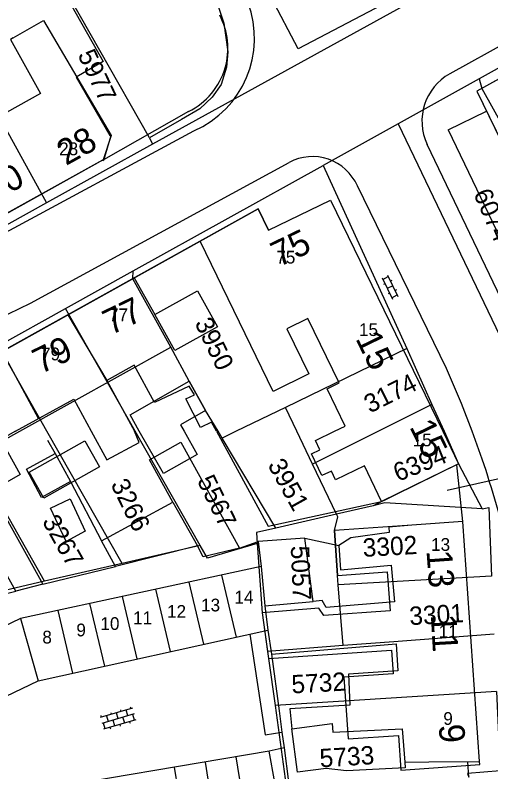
# Model space of a CAD drawing. Extents: x 148816 to 151297, y 399515 to 402500.
# Drawn here: x 150075.5 to 150122.1, y 399966.6 to 400040.8 of the extents above; entities that cross this region are included whole.
import ezdxf

# ---------------------------------------------------------------- set-up
doc = ezdxf.new("R2010")
doc.units = 0
for name, color, linetype in [('B01 Hoofdgebouw  [D] Norm', 7, 'Continuous'), ('B01 Hoofdgebouw  [T] Norm', 7, 'Continuous'), ('B01 hoofgebouw', 7, 'Continuous'), ('B02 Bijgebouw  [D] Norm', 7, 'Continuous'), ('B07 Tussenmuur  [D] Norm', 7, 'Continuous'), ('G01 perceelsgrens', 7, 'Continuous'), ('Q21 Lichtmast  Gem', 7, 'Continuous'), ('S02 Open verharding  Norm', 7, 'Continuous'), ('T04 Haag heg  [D] Gem', 7, 'Continuous'), ('V00 Kant verharding algemeen  [T] Norm', 7, 'Continuous'), ('Z01 perceelnummer', 7, 'Continuous'), ('Z02 huisnummer', 7, 'Continuous'), ('Z02 Huisnummer  [Tekst] Norm', 7, 'Continuous')]:
    doc.layers.add(name, color=color, linetype=linetype)

msp = doc.modelspace()

# ---------------------------------------------------------------- linework, layer by layer
at = {"layer": 'B01 Hoofdgebouw  [D] Norm'}
for points in [[(150089.203, 400011.428), (150093.387, 400013.755), (150095.347, 400010.23), (150091.163, 400007.903)], [(150091.769, 399998.936), (150097.495, 399988.553), (150093.962, 399987.692), (150093.404, 399988.761), (150085.371, 399986.735), (150083.977, 399989.254), (150090.972, 399993.062), (150088.691, 399997.209)], [(150076.644, 399996.281), (150079.442, 399997.83), (150080.962, 399995.081), (150078.114, 399993.508)], [(150080.934, 399993.377), (150082.403, 399990.222), (150080.521, 399989.207), (150079.001, 399992.464)], [(150100.412, 399968.636), (150075.704, 399964.466), (150076.711, 399958.311), (150101.52, 399962.506)]]:
    msp.add_lwpolyline(points, close=True, dxfattribs=at)
for points in [[(150095.261, 400000), (150094.753, 400000.902), (150093.69, 400000.385), (150092.244, 400003.168), (150093.104, 400003.582), (150092.564, 400004.416), (150089.172, 400002.813), (150087.185, 400006.482), (150084.504, 400004.986), (150087.214, 400000)], [(150075.565, 400000), (150081.291, 400003.156), (150082.98, 400000)], [(150075.565, 400000), (150074.133, 399999.183), (150076.008, 399995.773), (150073.159, 399994.123), (150078.253, 399985.013), (150075.583, 399984.329), (150071.731, 399991.226)], [(150082.98, 400000), (150084.523, 399997.214), (150087.677, 399998.889), (150087.214, 400000)], [(150095.261, 400000), (150100.32, 399990.712), (150111.437, 399993.114)], [(150114.4, 399990.81), (150112.136, 399990.597), (150112.186, 399990.089), (150108.424, 399989.559), (150107.254, 399988.797), (150107.403, 399986.406), (150112.384, 399986.884), (150112.709, 399983.298), (150105.999, 399982.72), (150105.619, 399983.407), (150104.73, 399983.306), (150103.926, 399989.538), (150099.326, 399989.212), (150099.627, 399986.745), (150076.062, 399981.658), (150066.576, 399977.116)], [(150058.071, 399966.088), (150077.78, 399975.553), (150100.278, 399980.513), (150100.63, 399978.148), (150112.855, 399979.178), (150113.029, 399976.507), (150108.2, 399976.207), (150108.322, 399973.155), (150102.451, 399972.805), (150102.652, 399970.847), (150106.591, 399971.376), (150106.666, 399970.512), (150113.452, 399970.835), (150113.724, 399967.577), (150116.05, 399967.6)]]:
    msp.add_lwpolyline(points, dxfattribs=at)
at = {"layer": 'B01 Hoofdgebouw  [T] Norm'}
for p, q in [((150141.8, 400044.98), (150120.75, 400033.32)), ((150081.499, 400034.694), (150084.812, 400028.99)), ((150120.75, 400033.32), (150124.26, 400026.13)), ((150084.812, 400028.99), (150084.905, 400028.958)), ((150084.08, 400026.58), (150073.17, 400020.49)), ((150084.08, 400026.58), (150084.173, 400026.548)), ((150100.34, 400019.72), (150106.42, 400022.65)), ((150106.42, 400022.65), (150117.43, 400000)), ((150060.19, 400000), (150099.35, 400021.79)), ((150099.35, 400021.79), (150100.34, 400019.72)), ((150119.39, 399991.16), (150114.4, 399990.81)), ((150121.04, 399967.65), (150119.39, 399991.16)), ((150116.05, 399967.6), (150121.04, 399967.65))]:
    msp.add_line(p, q, dxfattribs=at)
for points in [[(150068.641, 400039.806), (150078.854, 400045.595), (150084.158, 400036.238), (150081.499, 400034.694)], [(150084.812, 400028.99), (150084.905, 400028.958), (150084.173, 400026.548)], [(150117.429, 400000), (150118.98, 399996.81), (150111.437, 399993.114), (150109.742, 399996.603), (150106.93, 399995.236), (150106.508, 399996.104), (150105.588, 399995.657), (150104.553, 399997.786), (150105.386, 399998.191), (150104.951, 399999.086), (150106.832, 400000)]]:
    msp.add_lwpolyline(points, dxfattribs=at)
at = {"layer": 'B01 hoofgebouw'}
for points in [[(150144.23, 400040.61), (150141.8, 400044.98), (150120.75, 400033.32), (150124.26, 400026.13), (150124.09, 400025.97), (150128.5, 400018.09), (150131.27, 400019.64)], [(150075.34, 400038.54), (150075.082, 400038.392), (150078.015, 400033.103), (150071.305, 400029.382), (150063.11, 400044.161)], [(150075.34, 400038.54), (150078.32, 400040.25), (150084.95, 400028.97), (150084.17, 400026.59), (150073.17, 400020.49), (150069.73, 400026.7), (150068.87, 400026.22), (150072.31, 400020), (150037.55, 400000.75), (150035.13, 400005.12)], [(150100.341, 400019.72), (150106.42, 400022.65), (150117.429, 400000)], [(150100.341, 400019.72), (150099.351, 400021.79), (150060.192, 400000)], [(150106.832, 400000), (150107.865, 400000.502), (150106.084, 400004.165), (150107.288, 400004.751), (150104.222, 400011.058), (150102.157, 400010.054), (150104.315, 400005.615), (150100.803, 400003.909), (150093.653, 400018.619)], [(150075.994, 400000), (150090.797, 400008.237), (150087.061, 400014.951)], [(150087.694, 400000), (150086.785, 400001.594), (150092.566, 400004.893), (150094.191, 400002.045), (150091.715, 400000.632), (150092.076, 400000)], [(150037.39, 399981.59), (150038.694, 399979.245), (150075.994, 400000)], [(150090.064, 399995.846), (150087.694, 400000)], [(150092.076, 400000), (150093.37, 399997.732), (150090.064, 399995.846)], [(150114.49, 399994.61), (150111.437, 399993.114), (150109.742, 399996.603), (150106.93, 399995.236), (150106.508, 399996.104), (150105.588, 399995.657), (150104.553, 399997.786), (150105.386, 399998.191), (150104.951, 399999.086), (150106.832, 400000)], [(150117.429, 400000), (150118.98, 399996.81), (150114.49, 399994.61)], [(150076.912, 399995.996), (150082.363, 399999.062), (150083.797, 399996.513), (150078.346, 399993.447), (150076.912, 399995.996)], [(150116.05, 399967.6), (150121.04, 399967.65), (150119.39, 399991.16), (150114.4, 399990.81)], [(150114.4, 399990.81), (150106.807, 399990.277), (150107.116, 399985.874), (150111.993, 399986.216), (150112.261, 399982.401), (150105.774, 399981.946), (150105.27, 399982.654), (150099.723, 399982.193), (150100.368, 399977.719), (150112.391, 399978.562), (150112.555, 399976.228), (150107.744, 399975.891), (150108.168, 399969.843), (150113.089, 399970.188), (150113.327, 399966.792), (150121.062, 399967.335), (150121.04, 399967.65)]]:
    msp.add_lwpolyline(points, dxfattribs=at)
at = {"layer": 'B02 Bijgebouw  [D] Norm'}
for p, q in [((150095.75, 399985.908), (150097.177, 399979.829)), ((150092.55, 399985.217), (150093.981, 399979.125)), ((150089.295, 399984.515), (150090.728, 399978.408)), ((150086.027, 399983.809), (150087.464, 399977.688)), ((150082.832, 399983.119), (150084.272, 399976.984)), ((150079.703, 399982.444), (150081.146, 399976.295)), ((150076.062, 399981.658), (150077.78, 399975.553)), ((150097.137, 399968.083), (150098.143, 399961.935)), ((150094.145, 399967.578), (150095.151, 399961.429)), ((150091.109, 399967.066), (150092.115, 399960.916))]:
    msp.add_line(p, q, dxfattribs=at)
for points in [[(150090.972, 399993.062), (150093.404, 399988.761)], [(150099.627, 399986.745), (150099.977, 399982.879), (150100.278, 399980.513)], [(150099.977, 399982.879), (150104.73, 399983.306)]]:
    msp.add_lwpolyline(points, dxfattribs=at)
at = {"layer": 'B07 Tussenmuur  [D] Norm'}
for p, q in [((150087.199, 400015.029), (150089.203, 400011.428)), ((150087.199, 400015.029), (150089.203, 400011.428)), ((150077.812, 400001.239), (150074.244, 400007.845)), ((150077.812, 400001.239), (150074.244, 400007.845))]:
    msp.add_line(p, q, dxfattribs=at)
msp.add_lwpolyline([(150080.685, 400011.418), (150084.504, 400004.986)], dxfattribs=at)
msp.add_lwpolyline([(150080.685, 400011.418), (150084.504, 400004.986)], dxfattribs=at)
at = {"layer": 'G01 perceelsgrens'}
for points in [[(150070.311, 400093.431), (150072.021, 400088.838), (150075.48, 400081.91), (150095.399, 400041.747), (150095.983, 400039.981), (150096.375, 400037.181), (150096.249, 400035.687), (150095.73, 400033.978), (150094.849, 400032.748), (150093.622, 400031.596), (150091.837, 400030.559), (150088.71, 400028.765)], [(150088.71, 400028.765), (150078.962, 400045.889), (150073.614, 400042.961), (150068.705, 400040.287)], [(150115.147, 400042.587), (150088.986, 400028.14)], [(150068.705, 400040.287), (150073.143, 400032.247), (150078.605, 400022.382)], [(150125.76, 400037.174), (150120.99, 400034.535)], [(150120.99, 400034.535), (150113.052, 400030.143)], [(150120.99, 400034.535), (150121.266, 400033.606), (150127.125, 400023.029), (150126.065, 400022.442), (150127.698, 400019.524), (150130.195, 400014.798)], [(150113.052, 400030.143), (150105.721, 400026.043)], [(150113.052, 400030.143), (150123.378, 400008.595), (150127.587, 400008.897)], [(150088.71, 400028.765), (150088.986, 400028.14)], [(150088.986, 400028.14), (150078.605, 400022.382)], [(150087.097, 400015.714), (150105.721, 400026.043)], [(150105.721, 400026.043), (150113.907, 400008.116)], [(150078.605, 400022.382), (150072.901, 400019.218)], [(150080.453, 400012.029), (150087.097, 400015.714)], [(150095.411, 400000), (150094.191, 400002.045), (150092.566, 400004.893), (150090.797, 400008.237), (150087.061, 400014.951), (150087.097, 400015.714)], [(150073.864, 400008.374), (150080.453, 400012.029)], [(150087.293, 400000), (150080.453, 400012.029)], [(150078.635, 400000), (150073.864, 400008.374)], [(150113.907, 400008.116), (150102.006, 400002.344)], [(150113.907, 400008.116), (150116.368, 400002.631)], [(150102.006, 400002.344), (150097.171, 400000)], [(150103.128, 400000), (150102.006, 400002.344)], [(150116.368, 400002.631), (150111.117, 400000)], [(150116.368, 400002.631), (150117.549, 400000)], [(150078.415, 399985.296), (150070.081, 400000)], [(150086.012, 399987.052), (150078.635, 400000)], [(150093.651, 399988.818), (150087.293, 400000)], [(150095.806, 399999.338), (150095.411, 400000)], [(150097.171, 400000), (150095.806, 399999.338)], [(150104.674, 399996.772), (150103.128, 400000)], [(150111.117, 400000), (150104.674, 399996.772)], [(150117.549, 400000), (150118.98, 399996.81)], [(150101.076, 399990.508), (150095.806, 399999.338)], [(150118.98, 399996.81), (150110.6, 399992.704)], [(150118.98, 399996.81), (150121.273, 399992.407)], [(150107.017, 399991.878), (150104.674, 399996.772)], [(150110.6, 399992.704), (150107.017, 399991.878)], [(150121.273, 399992.407), (150111.754, 399992.97), (150110.6, 399992.704)], [(150121.273, 399992.407), (150121.924, 399992.524), (150122.215, 399985.802)], [(150107.017, 399991.878), (150101.076, 399990.508)], [(150107.19, 399984.944), (150107.116, 399985.874), (150106.807, 399990.277), (150107.15, 399991.601), (150107.017, 399991.878)], [(150101.076, 399990.508), (150099.176, 399990.07), (150099.252, 399988.987)], [(150093.651, 399988.818), (150086.012, 399987.052)], [(150099.252, 399988.987), (150094.369, 399987.556), (150093.651, 399988.818)], [(150099.252, 399988.987), (150099.723, 399982.193), (150100.265, 399978.433)], [(150086.012, 399987.052), (150078.415, 399985.296)], [(150122.215, 399985.802), (150107.19, 399984.944)], [(150078.415, 399985.296), (150070.88, 399983.554)], [(150107.664, 399978.996), (150107.19, 399984.944)], [(150122.462, 399980.111), (150112.617, 399979.373), (150107.664, 399978.996)], [(150107.664, 399978.996), (150100.265, 399978.433)], [(150100.265, 399978.433), (150100.368, 399977.719), (150100.998, 399973.112)], [(150122.705, 399974.484), (150100.998, 399973.112)], [(150122.705, 399974.484), (150123.041, 399966.715), (150119.847, 399966.465), (150119.97, 399966.09)], [(150100.998, 399973.112), (150102.08, 399965.208)]]:
    msp.add_lwpolyline(points, dxfattribs=at)
at = {"layer": 'Q21 Lichtmast  Gem'}
msp.add_lwpolyline([(150470.017, 401545.896), (150556.482, 401148.679), (150587.331, 401006.961), (150639.146, 400861.228), (150791.995, 400651.605), (150911.823, 400487.271), (150967.929, 400385.834), (150992.884, 400314.712), (150864.365, 400354.64), (150785.757, 400358.383), (150705.901, 400348.401), (150564.281, 400314.712), (150489.416, 400271.041), (150319.721, 400151.257), (150222.396, 400100.099), (150103.263, 400037.477), (150071.606, 400097.702), (150036.481, 400058.923), (149995.306, 400040.207), (149954.13, 400021.49), (149930.422, 400026.481), (149891.118, 400015.252), (149831.226, 399977.819), (149652.797, 400166.23)], dxfattribs=at)
at = {"layer": 'S02 Open verharding  Norm'}
for p, q in [((150111.482, 400015.02), (150112.498, 400012.957)), ((150111.548, 400014.886), (150112.087, 400015.151)), ((150112.02, 400015.285), (150113.036, 400013.222)), ((150112.442, 400014.768), (150112.307, 400014.702)), ((150111.769, 400014.437), (150111.634, 400014.371)), ((150112.528, 400014.253), (150111.99, 400013.989)), ((150112.884, 400013.871), (150112.749, 400013.805)), ((150112.211, 400013.54), (150112.076, 400013.474)), ((150112.431, 400013.091), (150112.97, 400013.356)), ((150087.03, 399972.872), (150083.863, 399971.944)), ((150084.966, 399972.267), (150084.924, 399972.411)), ((150085.615, 399971.832), (150085.446, 399972.408)), ((150085.926, 399972.548), (150085.884, 399972.692)), ((150086.575, 399972.113), (150086.406, 399972.689)), ((150086.886, 399972.83), (150086.843, 399972.974)), ((150084.007, 399971.986), (150083.965, 399972.13)), ((150087.198, 399972.296), (150084.032, 399971.368)), ((150087.367, 399971.72), (150084.2, 399970.792)), ((150084.487, 399972.126), (150084.655, 399971.551)), ((150085.304, 399971.116), (150085.135, 399971.691)), ((150086.264, 399971.397), (150086.095, 399971.973)), ((150087.223, 399971.678), (150087.054, 399972.254)), ((150084.344, 399970.834), (150084.176, 399971.41)), ((150084.824, 399970.975), (150084.866, 399970.831)), ((150085.784, 399971.256), (150085.826, 399971.112)), ((150086.743, 399971.538), (150086.786, 399971.394))]:
    msp.add_line(p, q, dxfattribs=at)
at = {"layer": 'T04 Haag heg  [D] Gem'}
for points in [[(150078.707, 399999.128), (150079.442, 399997.83)], [(150080.962, 399995.081), (150083.977, 399989.254)], [(150103.926, 399989.538), (150107.254, 399988.797)], [(150097.495, 399988.553), (150099.326, 399989.212)], [(150078.253, 399985.013), (150085.371, 399986.735)], [(150070.245, 399982.987), (150075.583, 399984.329)], [(150100.63, 399978.148), (150101.384, 399972.603), (150101.66, 399970.517)], [(150113.724, 399967.577), (150113.751, 399967.02), (150107.982, 399966.721), (150106, 399966.952), (150103.179, 399966.599), (150102.652, 399970.847)], [(150101.886, 399968.991), (150102.313, 399965.659), (150102.541, 399965.48), (150105.21, 399965.707), (150105.235, 399965.452), (150106.48, 399965.527)]]:
    msp.add_lwpolyline(points, dxfattribs=at)
at = {"layer": 'V00 Kant verharding algemeen  [T] Norm'}
for p, q in [((150242.999, 400104.125), (150118.119, 400035.039)), ((150092.53, 400031.34), (150084.189, 400026.601)), ((150117.97, 400029.55), (150121.7, 400031.37)), ((150068.471, 400016.166), (150093.043, 400029.445)), ((150117.97, 400029.55), (150127.88, 400008.77)), ((150124.69, 400009.71), (150115.903, 400028.117)), ((150077.03, 400012.542), (150102.382, 400026.348)), ((150117.78, 400006.14), (150109.058, 400024.054)), ((150071.562, 400009.899), (150077.03, 400012.542)), ((150119.27, 400002.705), (150117.78, 400006.14)), ((150120.315, 400000.025), (150119.27, 400002.705)), ((150121.3, 399997.25), (150120.315, 400000.025)), ((150119.39, 399991.16), (150118.81, 399996.71)), ((150119.97, 399966.09), (150119.87, 399967.6))]:
    msp.add_line(p, q, dxfattribs=at)
for points in [[(150098.524, 399980.108), (150100.033, 399970.264), (150101.66, 399970.517)], [(150101.66, 399970.517), (150101.886, 399968.991)], [(150101.886, 399968.991), (150100.412, 399968.636)]]:
    msp.add_lwpolyline(points, dxfattribs=at)
for centre, radius, start, end in [((150089.066, 400038.527), 9.914, 293.6478, 20.44539), ((150089.315, 400037.529), 7.058, 344.30504, 27.42389), ((150089.428, 400037.572), 6.961, 296.46129, 343.71721), ((150120.685, 400030.401), 5.3, 118.95793, 205.52908), ((150104.652, 400022.094), 4.822, 23.98455, 118.08806), ((150012.748, 399961.114), 114.409, 13.73519, 18.41193)]:
    msp.add_arc(centre, radius, start, end, dxfattribs=at)
at = {"layer": 'Z01 perceelnummer'}
msp.add_lwpolyline([(150126.296, 399996.084), (150117.845, 399994.185)], dxfattribs=at)

# ---------------------------------------------------------------- texts
for s, rotation, p in [('5977', 295.23462, (150081.621, 400036.902)), ('6074', 293.51456, (150120.396, 400023.296)), ('3950', 295.67386, (150093.087, 400010.614)), ('3174', 26.53932, (150110.284, 400001.732)), ('6394', 21.74799, (150113.025, 399995.034)), ('3951', 298.99898, (150100.23, 399996.699)), ('3266', 296.13197, (150084.857, 399994.806)), ('5567', 296.15798, (150093.322, 399995.163)), ('3267', 299.41082, (150078.13, 399991.175)), ('3302', 3.18304, (150109.63, 399987.683)), ('5057', 272.38594, (150102.532, 399988.755)), ('3301', 3.2754, (150114.196, 399980.996)), ('5732', 3.11272, (150102.646, 399974.301)), ('5733', 3.52944, (150105.417, 399967.058))]:
    msp.add_text(s, height=1.8, rotation=rotation, dxfattribs=at).set_placement(p)
at = {"layer": 'Z02 huisnummer'}
for s, rotation, p in [('28', 28.99898, (150080.507, 400025.989)), ('30', 28.99898, (150073.381, 400022.396)), ('75', 25.71951, (150101.367, 400016.052)), ('77', 25.71951, (150084.901, 400009.38)), ('15', 295.92419, (150108.841, 400009.09)), ('79', 25.71951, (150078.022, 400005.576)), ('15', 295.92419, (150114.127, 400000.452)), ('13', 274.01217, (150115.831, 399988.285)), ('11', 273.26885, (150116.254, 399982.021)), ('9', 274.01217, (150117.027, 399971.228))]:
    msp.add_text(s, height=2.5, rotation=rotation, dxfattribs=at).set_placement(p)
at = {"layer": 'Z02 Huisnummer  [Tekst] Norm'}
for s, p in [('28', (150079.845, 400027.05)), ('75', (150101.12, 400016.435)), ('77', (150084.732, 400010.784)), ('15', (150109.22, 400009.335)), ('79', (150078.075, 400006.949)), ('15', (150114.475, 399998.525)), ('13', (150116.285, 399988.28)), ('14', (150097.015, 399983.115)), ('13', (150093.751, 399982.347)), ('12', (150090.418, 399981.718)), ('11', (150087.084, 399981.089)), ('10', (150083.891, 399980.529)), ('9', (150081.532, 399979.9)), ('11', (150117.027, 399979.761)), ('8', (150078.198, 399979.201)), ('9', (150117.48, 399971.225))]:
    msp.add_text(s, height=1.25, dxfattribs=at).set_placement(p)

doc.saveas('drawing.dxf')
